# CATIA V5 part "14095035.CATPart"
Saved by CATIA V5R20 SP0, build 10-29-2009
Part number: 14095035
Definition: NONE
Nomenclature: 14095035
Source: Unknown
Description: 14095035
Bounding box of the stored display mesh (mm): x -17.5 to 70, y -61.5 to 51.6, z -51.6 to 51.6
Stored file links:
  C:\Users\Utente\Desktop\IO LAVORO\3D X SITO CF\X SITO\PLASTICA\RF2\14095035.CATPart
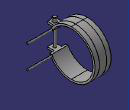
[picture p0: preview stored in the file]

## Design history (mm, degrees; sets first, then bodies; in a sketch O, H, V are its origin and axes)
Body1 "14095035" (main body)
  Solid1: solid without history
